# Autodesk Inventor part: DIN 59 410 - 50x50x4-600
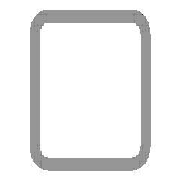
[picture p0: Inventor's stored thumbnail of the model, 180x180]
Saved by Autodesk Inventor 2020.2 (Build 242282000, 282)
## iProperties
Manager: www.cadconsulting.pl
Company: Fabian Stasiak CAD Consulting
Created: 2015-01
Part Number: DIN 59 410 - 50x50x4-600
Material: Stal, miękka
Description: Rurki stalowe o przekroju kwadratowym formowane na gorąco
Document SubType Name: Modellieren
Standard: DIN
Designer: F.Stasiak
Standards Organization: DIN
Language: pl-PL
Size Designation: 50x50x4
Categories: <MemberInstance><Categories><Category DisplayName="Kształtowniki konstrukcyjne" InternalName="089c4875-fa83-4c05-b084-43b9cc11f5ed" Mnemonic="GRDR"><CategoryPar
Stock Number: 50x50x4
Density: 7.85 g/cm^3
Appearance: Częściowo polerowana
Mass: 3327.03 g
Surface Area: 2133.03 cm^2
Volume: 423.826 cm^3
Catalog Web Link: www.expertbooks.pl
_CCFamilyMember: 40
_CCFamilyDisplayName: DIN 59410 (Kwadrat) - Rurki stalowe o przekroju kwadratowym formowane na gorąco
_FrameMemberDoc: Frame Member File
_Version: 15.0.0
_GetPNFromCC: 1
G_W: 50,000 mm
G_H: 50,000 mm
G_L: 600,000 mm
+9FEBDFFB-AECE-4B26-88CE-A005DC830838+CUTDETAIL3: Wytnij
+26759584-0CD6-4BB7-8DD2-50B0841671C7+CUTDETAIL4: Wytnij
IsCustomPart: 1
Author: F.Stasiak
Subject: Zbiór ćwiczeń. Autodesk Inventor 2020. Kurs Professional
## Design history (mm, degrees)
node "Płaszczyzna początkowa"
node "Płaszczyzna końcowa"
sketch "Szkic"
  geometry: L1 (-17, 25)-(17, 25); L2 (25, 17)-(25, -17); L3 (17, -25)-(-17, -25); L4 (-25, -17)-(-25, 17); L5 (-37.32, 0)-(37.32, 0) reference; L6 (0, -37.32)-(0, 37.32) reference; L7 (-17, 21)-(17, 21); L8 (21, 17)-(21, -17); L9 (17, -21)-(-17, -21); L10 (-21, -17)-(-21, 17); A1 r 8 centre (-17, 17) between (-17, 25) and (-25, 17); A2 r 8 centre (17, 17) between (25, 17) and (17, 25); A3 r 8 centre (17, -17) between (17, -25) and (25, -17); A4 r 8 centre (-17, -17) between (-25, -17) and (-17, -25); A5 r 4 centre (-17, 17) between (-17, 21) and (-21, 17); A6 r 4 centre (17, 17) between (21, 17) and (17, 21); A7 r 4 centre (17, -17) between (17, -21) and (21, -17); A8 r 4 centre (-17, -17) between (-21, -17) and (-17, -21); 3 further points
  constraints: 16 end point, 16 point on circle, 8 centre point, 8 tangent, 6 point on line, 4 parallel, 3 equal radius, 3 perpendicular, 1 horizontal, 7 other
  dimensions: "b" = 50 distance of point (-25, 25) point (25, 25); "msp_r" = 8 radius of A1 (= 2 x ParT); "d8" = 25 distance between parallel lines of L4 L6 (= d9); "d9" = 25 distance between parallel lines of L3 L5 (= 0.5 x b); "d10" = 4 distance between parallel lines of L3 L9 (= ParT)
extrude "Bryła" new body sketch "Szkic" taper "d4" = 0 deg; stored distance "NLG" = 10
node "Driven Length"
  sketch "Sketch2"
    geometry: L1 (0, 0)-(10, 0) reference
    constraints: 2 end point, 1 horizontal
  workplane "Work Plane3"
  sketch "Sketch3"
    geometry: L1 (-2, -25)-(12, -25) reference; L2 (-2, 575)-(12, 575) reference
    dimensions: "d14" = 600 distance between parallel lines of L1 L2 (derived)
node "Płaszczyzna konstrukcyjna6"
feature "Podział3"
node "Płaszczyzna konstrukcyjna7"
feature "Podział4"
body "Solid1"
other parameters: "ParT" = 4, "G_OFFSET_START" = 25 [user parameter; used in 1 equation term], "G_OFFSET_END" = -25 [user parameter; used in 1 equation term], "d11" = -25 (= -G_OFFSET_START), "d12" = 575 (= G_OFFSET_END + B_L), "G_L" = 600 (= d14) [user parameter], "d13" = 90 deg
